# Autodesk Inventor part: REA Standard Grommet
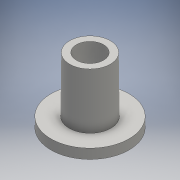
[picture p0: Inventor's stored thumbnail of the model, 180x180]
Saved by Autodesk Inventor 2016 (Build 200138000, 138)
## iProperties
Created: 2015-05
Part Number: REA Standard Grommet
Material: Generic
Document SubType Name: Modeling
Designer: Brett
Density: 1 g/cm^3
Appearance: Default
Author: Brett
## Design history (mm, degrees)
sketch "Sketch1"
  geometry: L1 (6, 0)-(6, 1.5); L2 (6, 1.5)-(3.2, 1.5); L3 (3.2, 1.5)-(3.126, 10); L4 (0, 5.169)-(0, -5.68); L5 (6, 0)-(2.009, 0) reference; L6 (2.009, 0)-(2.009, 0.646); L7 (2.009, 0.646)-(1.655, 1); L8 (1.655, 1)-(2.009, 1.354); L9 (2.009, 1.354)-(2.084, 10); L10 (3.126, 10)-(2.084, 10); 1 further point
  constraints: 20 end point, 2 horizontal, 2 point on line, 2 vertical, 1 perpendicular
  dimensions: "d0" = 6 distance of point (0, 0) L1.start; "d1" = 1.5 distance of L1.start L1.end; "d2" = 3.2 horizontal distance of point (0, 0) L2.end; "d4" = 0.5 deg angle of L4 L3; "d6" = 3.991 distance of L1.start L5.end; "d7" = 10 vertical distance of L3.end point (0, 0); "d8" = 45 deg angle of L6 L7; "d10" = 0.5 distance of L6.end L7.end; "d11" = 1 vertical distance of L7.end point (0, 0); "d12" = 0.5 deg angle of L4 L9
revolve "Revolution1" sketch "Sketch1" stored, may be unused: angle "d13" = 90 deg
body "Solid1"
